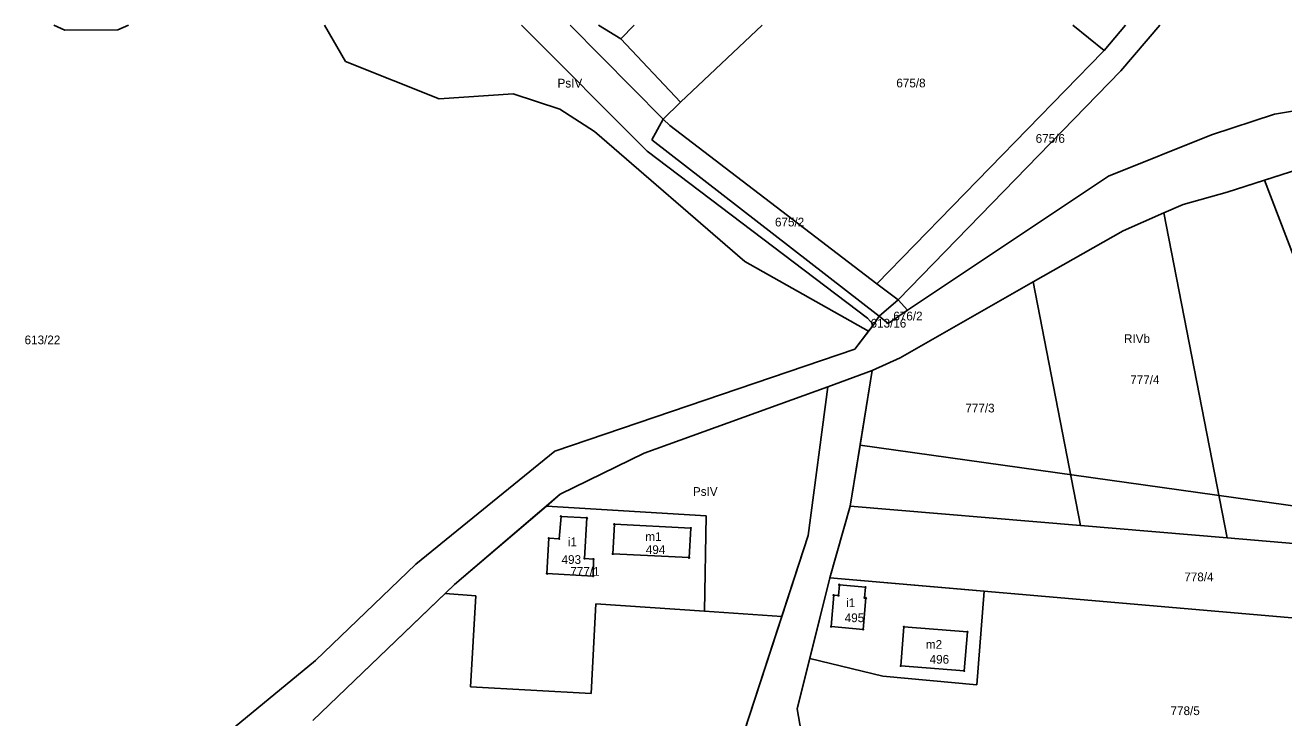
# Model space of a CAD drawing. Extents: x 7498273 to 7499989, y 5499795 to 5500810.
# Drawn here: x 7499065 to 7499281.1, y 5500690.6 to 5500809.6 of the extents above; entities that cross this region are included whole.
import ezdxf

# ---------------------------------------------------------------- set-up
doc = ezdxf.new("R2010")
doc.units = 0
for name, color, linetype in [('209-oznaczenie konturu klasyfikacyjnego', 7, 'Continuous'), ('211-numer działki ewidencyjnej', 7, 'Continuous'), ('217-kontur klasyfikacyjny', 7, 'Continuous'), ('218-kontur użytku gruntowego', 7, 'Continuous'), ('219-działka ewidencyjna', 7, 'Continuous'), ('312-budynek ewidencyjny', 7, 'Continuous'), ('312-oznaczenie budynku ewidencyjnego', 7, 'Continuous'), ('312-oznaczenie budynku ewidencyjnego-Atr117', 7, 'Continuous'), ('Punkt budynku', 7, 'Continuous')]:
    doc.layers.add(name, color=color, linetype=linetype)

# ---------------------------------------------------------------- blocks, each defined once
blk = doc.blocks.new('PUNKTBUD')
blk.add_circle((0, 0), 0.09)

msp = doc.modelspace()

# ---------------------------------------------------------------- linework, layer by layer
at = {"layer": '217-kontur klasyfikacyjny'}
for points in [[(7499071.79, 5500808.72), (7499069.878, 5500809.555)], [(7499080.88, 5500808.78), (7499071.79, 5500808.72)], [(7499082.696, 5500809.555), (7499080.88, 5500808.78)], [(7499119.96, 5500803.34), (7499116.341, 5500809.555)], [(7499163.427, 5500809.555), (7499167.24, 5500807.23)], [(7499167.24, 5500807.23), (7499177.52, 5500796.33)], [(7499136.03, 5500796.92), (7499119.96, 5500803.34)], [(7499148.78, 5500797.78), (7499136.03, 5500796.92)], [(7499156.8, 5500795.11), (7499148.78, 5500797.78)], [(7499279.46, 5500794.25), (7499294.96, 5500796.82)], [(7499162.73, 5500791.3), (7499156.8, 5500795.11)], [(7499177.52, 5500796.33), (7499174.51, 5500793.4)], [(7499174.51, 5500793.4), (7499172.56, 5500789.86)], [(7499268.66, 5500790.72), (7499279.46, 5500794.25)], [(7499188.56, 5500768.97), (7499162.73, 5500791.3)], [(7499251, 5500783.61), (7499268.66, 5500790.72)], [(7499172.56, 5500789.86), (7499211.63, 5500759.59)], [(7499283.69, 5500784.81), (7499277.76, 5500782.92)], [(7499216.45, 5500760.59), (7499251, 5500783.61)], [(7499277.76, 5500782.92), (7499271.37, 5500780.88)], [(7499282.77, 5500769.94), (7499277.76, 5500782.92)], [(7499271.37, 5500780.88), (7499263.79, 5500778.77)], [(7499260.51, 5500777.33), (7499253.5, 5500774.25)], [(7499263.79, 5500778.77), (7499260.51, 5500777.33)], [(7499253.5, 5500774.25), (7499238.05, 5500765.45)], [(7499209.8, 5500756.99), (7499188.56, 5500768.97)], [(7499238.05, 5500765.45), (7499215.23, 5500752.43)], [(7499213.18, 5500758.3), (7499216.45, 5500760.59)], [(7499209.8, 5500756.99), (7499210.66, 5500758.12)], [(7499210.66, 5500758.12), (7499211.63, 5500759.59)], [(7499211.63, 5500759.59), (7499213.18, 5500758.3)], [(7499207.45, 5500753.91), (7499209.8, 5500756.99)], [(7499155.92, 5500736.39), (7499207.45, 5500753.91)], [(7499215.23, 5500752.43), (7499210.41, 5500750.24)], [(7499210.41, 5500750.24), (7499202.79, 5500747.43)], [(7499208.32, 5500737.4), (7499210.41, 5500750.24)], [(7499202.79, 5500747.43), (7499171.26, 5500736.03)], [(7499202.79, 5500747.43), (7499199.42, 5500721.94)], [(7499132.06, 5500717), (7499155.92, 5500736.39)], [(7499206.62, 5500726.96), (7499208.32, 5500737.4)], [(7499296.97, 5500725.02), (7499208.32, 5500737.4)], [(7499171.26, 5500736.03), (7499156.85, 5500728.99)], [(7499156.85, 5500728.99), (7499154.47, 5500726.95)], [(7499154.47, 5500726.95), (7499181.89, 5500725.3)], [(7499203.15, 5500714.67), (7499206.62, 5500726.96)], [(7499181.89, 5500725.3), (7499181.6, 5500708.91)], [(7499199.42, 5500721.94), (7499194.89, 5500708.01)], [(7499114.85, 5500700.42), (7499132.06, 5500717)], [(7499199.68, 5500700.79), (7499203.15, 5500714.67)], [(7499203.15, 5500714.67), (7499229.64, 5500712.38)], [(7499137.1, 5500711.93), (7499114.34, 5500690.15)], [(7499142.36, 5500711.57), (7499137.1, 5500711.93)], [(7499141.45, 5500695.9), (7499142.36, 5500711.57)], [(7499229.64, 5500712.38), (7499228.39, 5500696.25)], [(7499162.94, 5500710.18), (7499162.15, 5500694.79)], [(7499181.6, 5500708.91), (7499162.94, 5500710.18)], [(7499194.89, 5500708.01), (7499181.6, 5500708.91)], [(7499187.59, 5500685.54), (7499194.89, 5500708.01)], [(7499090.15, 5500680.11), (7499114.85, 5500700.42)], [(7499197.52, 5500692.15), (7499199.68, 5500700.79)], [(7499212.23, 5500697.74), (7499199.68, 5500700.79)], [(7499228.39, 5500696.25), (7499212.23, 5500697.74)], [(7499162.15, 5500694.79), (7499141.45, 5500695.9)], [(7499199.73, 5500679.61), (7499197.52, 5500692.15)]]:
    msp.add_lwpolyline(points, dxfattribs=at)
at = {"layer": '218-kontur użytku gruntowego'}
for points in [[(7499069.878, 5500809.555), (7499071.79, 5500808.72)], [(7499071.79, 5500808.72), (7499080.88, 5500808.78)], [(7499080.88, 5500808.78), (7499082.696, 5500809.555)], [(7499119.96, 5500803.34), (7499116.341, 5500809.555)], [(7499163.427, 5500809.555), (7499167.24, 5500807.23)], [(7499167.24, 5500807.23), (7499177.52, 5500796.33)], [(7499136.03, 5500796.92), (7499119.96, 5500803.34)], [(7499148.78, 5500797.78), (7499136.03, 5500796.92)], [(7499156.8, 5500795.11), (7499148.78, 5500797.78)], [(7499279.46, 5500794.25), (7499294.96, 5500796.82)], [(7499162.73, 5500791.3), (7499156.8, 5500795.11)], [(7499177.52, 5500796.33), (7499174.51, 5500793.4)], [(7499174.51, 5500793.4), (7499172.56, 5500789.86)], [(7499268.66, 5500790.72), (7499279.46, 5500794.25)], [(7499188.56, 5500768.97), (7499162.73, 5500791.3)], [(7499251, 5500783.61), (7499268.66, 5500790.72)], [(7499172.56, 5500789.86), (7499211.63, 5500759.59)], [(7499283.69, 5500784.81), (7499277.76, 5500782.92)], [(7499216.45, 5500760.59), (7499251, 5500783.61)], [(7499277.76, 5500782.92), (7499271.37, 5500780.88)], [(7499277.76, 5500782.92), (7499282.77, 5500769.94)], [(7499271.37, 5500780.88), (7499263.79, 5500778.77)], [(7499260.51, 5500777.33), (7499253.5, 5500774.25)], [(7499263.79, 5500778.77), (7499260.51, 5500777.33)], [(7499253.5, 5500774.25), (7499238.05, 5500765.45)], [(7499209.8, 5500756.99), (7499188.56, 5500768.97)], [(7499238.05, 5500765.45), (7499215.23, 5500752.43)], [(7499213.18, 5500758.3), (7499216.45, 5500760.59)], [(7499209.8, 5500756.99), (7499210.66, 5500758.12)], [(7499210.66, 5500758.12), (7499211.63, 5500759.59)], [(7499211.63, 5500759.59), (7499213.18, 5500758.3)], [(7499207.45, 5500753.91), (7499209.8, 5500756.99)], [(7499155.92, 5500736.39), (7499207.45, 5500753.91)], [(7499215.23, 5500752.43), (7499210.41, 5500750.24)], [(7499210.41, 5500750.24), (7499202.79, 5500747.43)], [(7499210.41, 5500750.24), (7499208.32, 5500737.4)], [(7499202.79, 5500747.43), (7499171.26, 5500736.03)], [(7499199.42, 5500721.94), (7499202.79, 5500747.43)], [(7499132.06, 5500717), (7499155.92, 5500736.39)], [(7499208.32, 5500737.4), (7499206.62, 5500726.96)], [(7499208.32, 5500737.4), (7499296.97, 5500725.02)], [(7499171.26, 5500736.03), (7499156.85, 5500728.99)], [(7499156.85, 5500728.99), (7499154.47, 5500726.95)], [(7499154.47, 5500726.95), (7499138.71, 5500713.47)], [(7499181.89, 5500725.3), (7499154.47, 5500726.95)], [(7499206.62, 5500726.96), (7499203.15, 5500714.67)], [(7499181.6, 5500708.91), (7499181.89, 5500725.3)], [(7499194.89, 5500708.01), (7499199.42, 5500721.94)], [(7499114.85, 5500700.42), (7499132.06, 5500717)], [(7499203.15, 5500714.67), (7499199.68, 5500700.79)], [(7499229.64, 5500712.38), (7499203.15, 5500714.67)], [(7499138.71, 5500713.47), (7499137.1, 5500711.93)], [(7499137.1, 5500711.93), (7499114.34, 5500690.15)], [(7499137.1, 5500711.93), (7499142.36, 5500711.57)], [(7499142.36, 5500711.57), (7499141.45, 5500695.9)], [(7499228.39, 5500696.25), (7499229.64, 5500712.38)], [(7499162.15, 5500694.79), (7499162.94, 5500710.18)], [(7499162.94, 5500710.18), (7499181.6, 5500708.91)], [(7499181.6, 5500708.91), (7499194.89, 5500708.01)], [(7499194.89, 5500708.01), (7499187.59, 5500685.54)], [(7499090.15, 5500680.11), (7499114.85, 5500700.42)], [(7499199.68, 5500700.79), (7499197.52, 5500692.15)], [(7499199.68, 5500700.79), (7499212.23, 5500697.74)], [(7499212.23, 5500697.74), (7499228.39, 5500696.25)], [(7499141.45, 5500695.9), (7499162.15, 5500694.79)], [(7499197.52, 5500692.15), (7499199.73, 5500679.61)]]:
    msp.add_lwpolyline(points, dxfattribs=at)
at = {"layer": '219-działka ewidencyjna'}
for points in [[(7499150.174, 5500809.555), (7499171.8, 5500787.92)], [(7499158.56, 5500809.555), (7499174.51, 5500793.4)], [(7499167.24, 5500807.23), (7499169.559, 5500809.555)], [(7499177.52, 5500796.33), (7499191.508, 5500809.555)], [(7499244.848, 5500809.555), (7499250.24, 5500805.21)], [(7499253.932, 5500809.555), (7499250.24, 5500805.21)], [(7499253.1, 5500801.74), (7499259.806, 5500809.555)], [(7499167.24, 5500807.23), (7499177.52, 5500796.33)], [(7499211.22, 5500765.13), (7499250.02, 5500804.96)], [(7499250.02, 5500804.96), (7499250.24, 5500805.21)], [(7499214.87, 5500762.39), (7499253.1, 5500801.74)], [(7499294.96, 5500796.82), (7499279.46, 5500794.25)], [(7499177.52, 5500796.33), (7499174.51, 5500793.4)], [(7499172.56, 5500789.86), (7499174.51, 5500793.4)], [(7499174.51, 5500793.4), (7499175.69, 5500792.33)], [(7499268.66, 5500790.72), (7499279.46, 5500794.25)], [(7499211.22, 5500765.13), (7499175.69, 5500792.33)], [(7499251, 5500783.61), (7499268.66, 5500790.72)], [(7499172.56, 5500789.86), (7499211.63, 5500759.59)], [(7499171.8, 5500787.92), (7499209.58, 5500759.21)], [(7499271.37, 5500780.88), (7499283.69, 5500784.81)], [(7499216.45, 5500760.59), (7499251, 5500783.61)], [(7499263.79, 5500778.77), (7499271.37, 5500780.88)], [(7499253.5, 5500774.25), (7499260.51, 5500777.33)], [(7499260.51, 5500777.33), (7499263.79, 5500778.77)], [(7499260.51, 5500777.33), (7499271.38, 5500721.51)], [(7499238.05, 5500765.45), (7499253.5, 5500774.25)], [(7499211.22, 5500765.13), (7499214.87, 5500762.39)], [(7499215.23, 5500752.43), (7499238.05, 5500765.45)], [(7499238.05, 5500765.45), (7499246.19, 5500723.64)], [(7499211.63, 5500759.59), (7499214.87, 5500762.39)], [(7499214.87, 5500762.39), (7499216.45, 5500760.59)], [(7499213.18, 5500758.3), (7499216.45, 5500760.59)], [(7499210.66, 5500758.12), (7499207.45, 5500753.91)], [(7499210.66, 5500758.12), (7499209.58, 5500759.21)], [(7499210.66, 5500758.12), (7499211.63, 5500759.59)], [(7499211.63, 5500759.59), (7499213.18, 5500758.3)], [(7499155.92, 5500736.39), (7499207.45, 5500753.91)], [(7499210.41, 5500750.24), (7499215.23, 5500752.43)], [(7499202.79, 5500747.43), (7499210.41, 5500750.24)], [(7499206.62, 5500726.96), (7499210.41, 5500750.24)], [(7499171.26, 5500736.03), (7499202.79, 5500747.43)], [(7499199.42, 5500721.94), (7499202.79, 5500747.43)], [(7499155.92, 5500736.39), (7499132.06, 5500717)], [(7499156.85, 5500728.99), (7499171.26, 5500736.03)], [(7499138.71, 5500713.47), (7499156.85, 5500728.99)], [(7499203.15, 5500714.67), (7499206.62, 5500726.96)], [(7499206.62, 5500726.96), (7499246.19, 5500723.64)], [(7499246.19, 5500723.64), (7499271.38, 5500721.51)], [(7499187.59, 5500685.54), (7499199.42, 5500721.94)], [(7499271.38, 5500721.51), (7499310.91, 5500718.15)], [(7499114.85, 5500700.42), (7499132.06, 5500717)], [(7499197.52, 5500692.15), (7499203.15, 5500714.67)], [(7499203.15, 5500714.67), (7499324.84, 5500704.13)], [(7499114.34, 5500690.15), (7499138.71, 5500713.47)], [(7499090.15, 5500680.11), (7499114.85, 5500700.42)], [(7499197.52, 5500692.15), (7499199.73, 5500679.61)]]:
    msp.add_lwpolyline(points, dxfattribs=at)
at = {"layer": '312-budynek ewidencyjny'}
for points in [[(7499156.68, 5500721.35), (7499156.98, 5500725.19)], [(7499156.98, 5500725.19), (7499161.42, 5500724.92)], [(7499161.42, 5500724.92), (7499160.99, 5500717.97)], [(7499165.88, 5500718.77), (7499166.14, 5500723.85)], [(7499166.14, 5500723.85), (7499179.27, 5500723.19)], [(7499154.57, 5500715.39), (7499154.88, 5500721.44)], [(7499154.88, 5500721.44), (7499156.68, 5500721.35)], [(7499179.27, 5500723.19), (7499178.97, 5500718.11)], [(7499160.99, 5500717.97), (7499162.54, 5500717.87)], [(7499162.54, 5500717.87), (7499162.48, 5500714.94)], [(7499178.97, 5500718.11), (7499165.88, 5500718.77)], [(7499162.48, 5500714.94), (7499154.57, 5500715.39)], [(7499204.62, 5500711.59), (7499204.77, 5500713.44)], [(7499204.77, 5500713.44), (7499209.26, 5500713.03)], [(7499209.26, 5500713.03), (7499209.1, 5500711.2)], [(7499203.37, 5500706.27), (7499203.8, 5500711.66)], [(7499203.8, 5500711.66), (7499204.62, 5500711.59)], [(7499209.32, 5500711.18), (7499208.85, 5500705.78)], [(7499209.1, 5500711.2), (7499209.32, 5500711.18)], [(7499208.85, 5500705.78), (7499203.37, 5500706.27)], [(7499215.31, 5500699.52), (7499215.85, 5500706.24)], [(7499215.85, 5500706.24), (7499226.76, 5500705.36)], [(7499226.76, 5500705.36), (7499226.22, 5500698.65)], [(7499226.22, 5500698.65), (7499215.31, 5500699.52)]]:
    msp.add_lwpolyline(points, dxfattribs=at)

# ---------------------------------------------------------------- block references
at = {"layer": 'Punkt budynku'}
for p in [(7499156.98, 5500725.19), (7499161.42, 5500724.92), (7499166.14, 5500723.85), (7499179.27, 5500723.19), (7499154.88, 5500721.44), (7499156.68, 5500721.35), (7499160.99, 5500717.97), (7499162.54, 5500717.87), (7499165.88, 5500718.77), (7499178.97, 5500718.11), (7499154.57, 5500715.39), (7499162.48, 5500714.94), (7499204.77, 5500713.44), (7499209.26, 5500713.03), (7499203.8, 5500711.66), (7499204.62, 5500711.59), (7499209.1, 5500711.2), (7499209.32, 5500711.18), (7499203.37, 5500706.27), (7499215.85, 5500706.24), (7499208.85, 5500705.78), (7499226.76, 5500705.36), (7499215.31, 5500699.52), (7499226.22, 5500698.65)]:
    msp.add_blockref('PUNKTBUD', p, dxfattribs=at)

# ---------------------------------------------------------------- texts
at = {"layer": '209-oznaczenie konturu klasyfikacyjnego'}
for s, p in [('PsIV', (7499156.38, 5500798.85)), ('RIVb', (7499253.65, 5500754.97)), ('PsIV', (7499179.63, 5500728.72))]:
    msp.add_text(s, height=1.5, dxfattribs=at).set_placement(p)
at = {"layer": '211-numer działki ewidencyjnej'}
for s, p in [('675/8', (7499214.56, 5500798.87)), ('675/6', (7499238.48, 5500789.35)), ('675/2', (7499193.72, 5500774.99)), ('676/2', (7499214.04, 5500758.85)), ('613/16', (7499210.13, 5500757.62)), ('613/22', (7499064.87, 5500754.75)), ('777/4', (7499254.72, 5500747.92)), ('777/3', (7499226.41, 5500743.05)), ('777/1', (7499158.57, 5500714.99)), ('778/4', (7499264, 5500714.05)), ('778/5', (7499261.64, 5500691.07))]:
    msp.add_text(s, height=1.5, dxfattribs=at).set_placement(p)
at = {"layer": '312-oznaczenie budynku ewidencyjnego'}
for s, p in [('494', (7499171.54, 5500718.73)), ('493', (7499157.07, 5500717.03)), ('495', (7499205.69, 5500707.03)), ('496', (7499220.27, 5500699.9))]:
    msp.add_text(s, height=1.5, dxfattribs=at).set_placement(p)
at = {"layer": '312-oznaczenie budynku ewidencyjnego-Atr117'}
for s, p in [('i1', (7499158.142, 5500720.07)), ('m1', (7499171.455, 5500720.98)), ('i1', (7499205.932, 5500709.61)), ('m2', (7499219.626, 5500702.45))]:
    msp.add_text(s, height=1.5, dxfattribs=at).set_placement(p)

doc.saveas('drawing.dxf')
